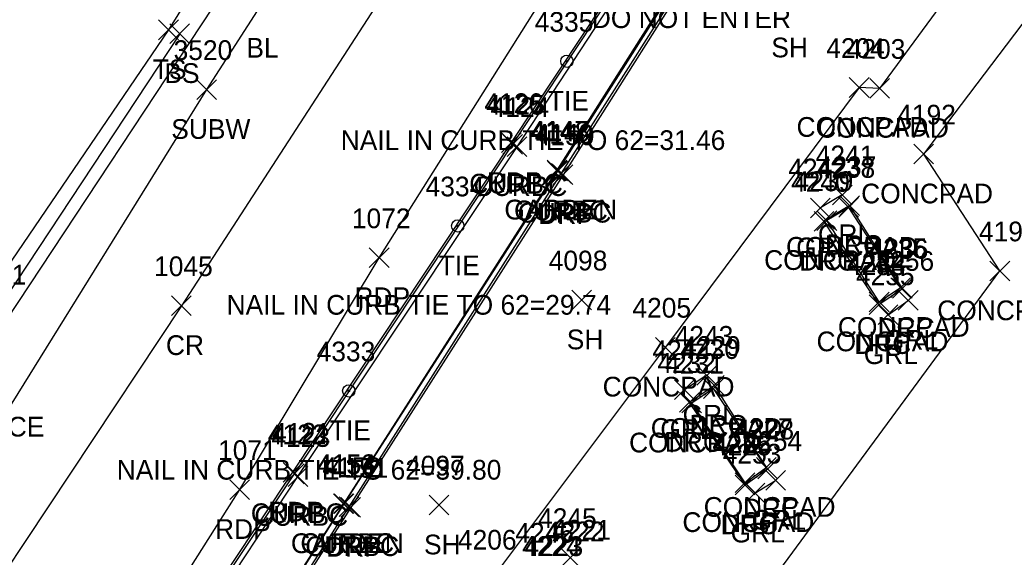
# Model space of a CAD drawing. Extents: x 1634209 to 1639641, y 608564 to 612258.
# Drawn here: x 1639153.3 to 1639254.2, y 611311.3 to 611365.7 of the extents above; entities that cross this region are included whole.
import ezdxf

# ---------------------------------------------------------------- set-up
doc = ezdxf.new("R2010")
doc.units = 0
for name, color, linetype in [('C_A', 7, 'Continuous'), ('C_C', 7, 'Continuous'), ('C_I', 7, 'Continuous'), ('CBP', 7, 'Continuous'), ('L_A', 7, 'Continuous'), ('L_I', 7, 'Continuous'), ('L_TIC', 7, 'Continuous'), ('LAPB', 7, 'Continuous'), ('LELB', 7, 'Continuous'), ('LS', 7, 'Continuous'), ('M_C', 7, 'Continuous'), ('P_A', 7, 'Continuous'), ('P_I', 7, 'Continuous'), ('P_TIC', 7, 'Continuous'), ('PET', 7, 'Continuous'), ('PRC', 7, 'Continuous'), ('R_A', 7, 'Continuous'), ('R_I', 7, 'Continuous'), ('R_TIC', 7, 'Continuous'), ('RC', 7, 'Continuous'), ('RDP', 7, 'Continuous'), ('RGR', 7, 'Continuous'), ('S_C', 7, 'Continuous'), ('U_A', 7, 'Continuous'), ('U_I', 7, 'Continuous'), ('U_TIC', 7, 'Continuous'), ('UW', 7, 'Continuous')]:
    doc.layers.add(name, color=color, linetype=linetype)

msp = doc.modelspace()

# ---------------------------------------------------------------- linework, layer by layer
at = {"layer": 'CBP'}
for centre, radius in [((1639208.81, 611361.54), 0.625), ((1639208.81, 611361.54), 0.0833), ((1639197.74, 611344.84), 0.625), ((1639197.74, 611344.84), 0.0833), ((1639186.69, 611328.11), 0.625), ((1639186.69, 611328.11), 0.0833)]:
    msp.add_circle(centre, radius, dxfattribs=at)
at = {"layer": 'L_TIC'}
for points in [[(1639167.4, 611363.73), (1639169.4, 611365.73)], [(1639169.4, 611363.73), (1639167.4, 611365.73)], [(1639168.54, 611363.34), (1639170.54, 611365.34)], [(1639170.54, 611363.34), (1639168.54, 611365.34)], [(1639237.46, 611357.88), (1639239.46, 611359.88)], [(1639239.46, 611357.88), (1639237.46, 611359.88)], [(1639239.54, 611357.79), (1639241.54, 611359.79)], [(1639241.54, 611357.79), (1639239.54, 611359.79)], [(1639244.01, 611351.13), (1639246.01, 611353.13)], [(1639246.01, 611351.13), (1639244.01, 611353.13)], [(1639206.8, 611349.5), (1639208.8, 611351.5)], [(1639208.8, 611349.5), (1639206.8, 611351.5)], [(1639236.4, 611345.72), (1639238.4, 611347.72)], [(1639238.4, 611345.72), (1639236.4, 611347.72)], [(1639234.18, 611344.38), (1639236.18, 611346.38)], [(1639236.18, 611344.38), (1639234.18, 611346.38)], [(1639234.18, 611344.38), (1639236.18, 611346.38)], [(1639236.18, 611344.38), (1639234.18, 611346.38)], [(1639251.73, 611339.28), (1639253.73, 611341.28)], [(1639253.73, 611339.28), (1639251.73, 611341.28)], [(1639241.66, 611337.59), (1639243.66, 611339.59)], [(1639243.66, 611337.59), (1639241.66, 611339.59)], [(1639209.31, 611336.33), (1639211.31, 611338.33)], [(1639211.31, 611336.33), (1639209.31, 611338.33)], [(1639239.49, 611336.13), (1639241.49, 611338.13)], [(1639241.49, 611336.13), (1639239.49, 611338.13)], [(1639239.49, 611336.13), (1639241.49, 611338.13)], [(1639241.49, 611336.13), (1639239.49, 611338.13)], [(1639217.8, 611331.54), (1639219.8, 611333.54)], [(1639219.8, 611331.54), (1639217.8, 611333.54)], [(1639222.67, 611327.35), (1639224.67, 611329.35)], [(1639224.67, 611327.35), (1639222.67, 611329.35)], [(1639220.48, 611325.87), (1639222.48, 611327.87)], [(1639222.48, 611325.87), (1639220.48, 611327.87)], [(1639220.48, 611325.87), (1639222.48, 611327.87)], [(1639222.48, 611325.87), (1639220.48, 611327.87)], [(1639228.04, 611319.34), (1639230.04, 611321.34)], [(1639230.04, 611319.34), (1639228.04, 611321.34)], [(1639225.88, 611317.8), (1639227.88, 611319.8)], [(1639227.88, 611317.8), (1639225.88, 611319.8)], [(1639225.88, 611317.8), (1639227.88, 611319.8)], [(1639227.88, 611317.8), (1639225.88, 611319.8)], [(1639185.15, 611315.66), (1639187.15, 611317.66)], [(1639187.15, 611315.66), (1639185.15, 611317.66)], [(1639194.84, 611315.53), (1639196.84, 611317.53)], [(1639196.84, 611315.53), (1639194.84, 611317.53)]]:
    msp.add_lwpolyline(points, dxfattribs=at)
at = {"layer": 'LAPB'}
msp.add_lwpolyline([(1639223.72, 611375.64), (1639207.8, 611350.5), (1639186.15, 611316.66), (1639169.99, 611291.33), (1639168.06, 611284.08), (1639167.91, 611278.79), (1639169.16, 611272.05), (1639187.9, 611242.79)], dxfattribs=at)
at = {"layer": 'LELB'}
for points in [[(1639184.5, 611390.62), (1639168.4, 611364.73), (1639149.1, 611336.39), (1639141.99, 611332.95), (1639134.34, 611331.83), (1639128.54, 611335.11), (1639121.61, 611339.72), (1639110.96, 611351.76), (1639096.78, 611371.21), (1639095.54, 611383.49), (1639101.79, 611394.14), (1639116.54, 611418.41), (1639131.91, 611444.98), (1639113.36, 611469.05), (1639093.12, 611490.67), (1639071.05, 611509.19), (1639055.5, 611526.42)], [(1639169.54, 611364.34), (1639150.74, 611335.9), (1639150.02, 611334.68), (1639147.96, 611333.12), (1639142.59, 611331.2), (1639134.1, 611329.89), (1639127.41, 611331.58), (1639119.27, 611337.17), (1639108.26, 611349.25)]]:
    msp.add_lwpolyline(points, dxfattribs=at)
at = {"layer": 'LS'}
for points in [[(1639197.35, 611268.33), (1639199.31, 611268.39), (1639210.97, 611284.28), (1639226, 611303.95), (1639252.73, 611340.28), (1639245.01, 611352.13), (1639262.63, 611375.38), (1639283.99, 611360.32), (1639285.88, 611360.67), (1639299.25, 611379.23), (1639299.14, 611381.16), (1639265.73, 611405.38), (1639263.88, 611405.03), (1639250.44, 611386.61), (1639250.46, 611384.53), (1639256.24, 611380.17), (1639240.54, 611358.79), (1639238.46, 611358.88), (1639218.8, 611332.54), (1639201.15, 611309.01), (1639184.63, 611286.63), (1639191.26, 611276.75)], [(1639240.49, 611337.13), (1639242.66, 611338.59), (1639237.4, 611346.72), (1639235.18, 611345.38)], [(1639240.49, 611337.13), (1639235.18, 611345.38)], [(1639226.88, 611318.8), (1639229.04, 611320.34), (1639223.67, 611328.35), (1639221.48, 611326.87)], [(1639226.88, 611318.8), (1639221.48, 611326.87)]]:
    msp.add_lwpolyline(points, dxfattribs=at)
at = {"layer": 'P_TIC'}
for points in [[(1639202.19, 611352.29), (1639204.19, 611354.29)], [(1639204.19, 611352.29), (1639202.19, 611354.29)], [(1639188.77, 611340.61), (1639190.77, 611342.61)], [(1639190.77, 611340.61), (1639188.77, 611342.61)], [(1639168.71, 611335.75), (1639170.71, 611337.75)], [(1639170.71, 611335.75), (1639168.71, 611337.75)], [(1639180.02, 611318.86), (1639182.02, 611320.86)], [(1639182.02, 611318.86), (1639180.02, 611320.86)], [(1639174.63, 611317.1), (1639176.63, 611319.1)], [(1639176.63, 611317.1), (1639174.63, 611319.1)]]:
    msp.add_lwpolyline(points, dxfattribs=at)
at = {"layer": 'PET'}
for points in [[(1639227.99, 611172.98), (1639228.32, 611174.39), (1639214.9, 611192.14), (1639202.86, 611208.11), (1639190.66, 611227), (1639183.08, 611239.21), (1639162.79, 611271), (1639160.92, 611274.86), (1639160.06, 611279.39), (1639160.11, 611285.35), (1639161.86, 611291.07), (1639181.02, 611319.86), (1639203.19, 611353.29), (1639219.74, 611378.25), (1639229.46, 611393.47), (1639239.19, 611407.62), (1639252.49, 611428.76), (1639267.88, 611454.5), (1639285.6, 611485.31)], [(1638854.83, 610853.22), (1638885.37, 610909), (1638902.82, 610937.28), (1638929.33, 610982.56), (1638950.92, 611019.42), (1638971.29, 611051.92), (1639000.04, 611096.96), (1639023.57, 611133.7), (1639039.12, 611159.19), (1639064.62, 611197.78), (1639080.51, 611223.3), (1639114.23, 611277.34), (1639131.17, 611302.28), (1639149.64, 611331.79), (1639176.42, 611372.35), (1639193.48, 611398.88), (1639220.96, 611441.47), (1639247.22, 611483.75)], [(1638878.4, 610839.82), (1638902.26, 610883.1), (1638925.76, 610925.06), (1638957.25, 610978.12), (1638978.73, 611014.12), (1639004.29, 611055.32), (1639040.97, 611112.28), (1639073.41, 611162.89), (1639072.72, 611163.46), (1639102.57, 611207.56), (1639124.27, 611240.99), (1639140.69, 611264.29), (1639156.2, 611287.4), (1639175.63, 611318.1), (1639189.77, 611341.61), (1639219.88, 611389.38), (1639245.26, 611428.04), (1639265.27, 611462.65)]]:
    msp.add_lwpolyline(points, dxfattribs=at)
at = {"layer": 'PRC'}
msp.add_lwpolyline([(1639250.46, 611462.84), (1639222.36, 611418.18), (1639195.34, 611376.28), (1639169.71, 611336.75), (1639147.17, 611302.78), (1639120.59, 611261.16), (1639092.55, 611217.83), (1639063.71, 611172.41), (1639032.46, 611123.7), (1639004.79, 611080.3), (1638977.88, 611037.27), (1638950.44, 610992.13), (1638925.96, 610950.29), (1638900.29, 610905.36), (1638879.75, 610869.2), (1638867.15, 610846.08)], dxfattribs=at)
at = {"layer": 'R_TIC'}
for points in [[(1639202.32, 611352.13), (1639204.32, 611354.13)], [(1639204.32, 611352.13), (1639202.32, 611354.13)], [(1639202.76, 611351.88), (1639204.76, 611353.88)], [(1639204.76, 611351.88), (1639202.76, 611353.88)], [(1639206.86, 611349.41), (1639208.86, 611351.41)], [(1639208.86, 611349.41), (1639206.86, 611351.41)], [(1639207.24, 611349.18), (1639209.24, 611351.18)], [(1639209.24, 611349.18), (1639207.24, 611351.18)], [(1639207.43, 611349.03), (1639209.43, 611351.03)], [(1639209.43, 611349.03), (1639207.43, 611351.03)], [(1639235.74, 611346.99), (1639237.74, 611348.99)], [(1639237.74, 611346.99), (1639235.74, 611348.99)], [(1639233.53, 611345.66), (1639235.53, 611347.66)], [(1639235.53, 611345.66), (1639233.53, 611347.66)], [(1639236.51, 611345.9), (1639238.51, 611347.9)], [(1639238.51, 611345.9), (1639236.51, 611347.9)], [(1639233.89, 611344.31), (1639235.89, 611346.31)], [(1639235.89, 611344.31), (1639233.89, 611346.31)], [(1639233.89, 611344.31), (1639235.89, 611346.31)], [(1639235.89, 611344.31), (1639233.89, 611346.31)], [(1639241.84, 611337.51), (1639243.84, 611339.51)], [(1639243.84, 611337.51), (1639241.84, 611339.51)], [(1639242.43, 611336.29), (1639244.43, 611338.29)], [(1639244.43, 611336.29), (1639242.43, 611338.29)], [(1639239.47, 611335.86), (1639241.47, 611337.86)], [(1639241.47, 611335.86), (1639239.47, 611337.86)], [(1639239.47, 611335.86), (1639241.47, 611337.86)], [(1639241.47, 611335.86), (1639239.47, 611337.86)], [(1639240.39, 611334.83), (1639242.39, 611336.83)], [(1639242.39, 611334.83), (1639240.39, 611336.83)], [(1639222.01, 611328.69), (1639224.01, 611330.69)], [(1639224.01, 611328.69), (1639222.01, 611330.69)], [(1639219.74, 611327.23), (1639221.74, 611329.23)], [(1639221.74, 611327.23), (1639219.74, 611329.23)], [(1639222.77, 611327.66), (1639224.77, 611329.66)], [(1639224.77, 611327.66), (1639222.77, 611329.66)], [(1639220.25, 611325.94), (1639222.25, 611327.94)], [(1639222.25, 611325.94), (1639220.25, 611327.94)], [(1639220.25, 611325.94), (1639222.25, 611327.94)], [(1639222.25, 611325.94), (1639220.25, 611327.94)], [(1639228.17, 611319.19), (1639230.17, 611321.19)], [(1639230.17, 611319.19), (1639228.17, 611321.19)], [(1639180.17, 611318.7), (1639182.17, 611320.7)], [(1639182.17, 611318.7), (1639180.17, 611320.7)], [(1639180.53, 611318.43), (1639182.53, 611320.43)], [(1639182.53, 611318.43), (1639180.53, 611320.43)], [(1639228.99, 611318.03), (1639230.99, 611320.03)], [(1639230.99, 611318.03), (1639228.99, 611320.03)], [(1639225.89, 611317.57), (1639227.89, 611319.57)], [(1639227.89, 611317.57), (1639225.89, 611319.57)], [(1639225.89, 611317.57), (1639227.89, 611319.57)], [(1639227.89, 611317.57), (1639225.89, 611319.57)], [(1639226.88, 611316.74), (1639228.88, 611318.74)], [(1639228.88, 611316.74), (1639226.88, 611318.74)], [(1639185.2, 611315.67), (1639187.2, 611317.67)], [(1639187.2, 611315.67), (1639185.2, 611317.67)], [(1639185.7, 611315.36), (1639187.7, 611317.36)], [(1639187.7, 611315.36), (1639185.7, 611317.36)], [(1639185.89, 611315.3), (1639187.89, 611317.3)], [(1639187.89, 611315.3), (1639185.89, 611317.3)], [(1639208.15, 611310.2), (1639210.15, 611312.2)], [(1639210.15, 611310.2), (1639208.15, 611312.2)]]:
    msp.add_lwpolyline(points, dxfattribs=at)
at = {"layer": 'RC'}
for points in [[(1639183.21, 611239.37), (1639162.96, 611271.11), (1639161.11, 611274.87), (1639160.3, 611279.33), (1639160.35, 611285.37), (1639162.06, 611290.92), (1639181.17, 611319.7), (1639203.32, 611353.13), (1639219.91, 611378.2)], [(1639183.57, 611239.62), (1639163.34, 611271.33), (1639161.58, 611275.05), (1639160.84, 611279.26), (1639160.77, 611285.27), (1639162.51, 611290.63), (1639181.53, 611319.43), (1639203.76, 611352.88), (1639220.25, 611377.98)], [(1639223.9, 611375.6), (1639207.86, 611350.41), (1639186.2, 611316.67), (1639170.12, 611291.28), (1639168.12, 611284.06), (1639167.97, 611278.79), (1639169.31, 611272.15), (1639188.08, 611242.69), (1639188.48, 611241.05), (1639187.63, 611239.54), (1639186.19, 611238.72), (1639184.76, 611238.74)], [(1639223.9, 611374.83), (1639208.24, 611350.18), (1639186.7, 611316.36), (1639170.39, 611290.97), (1639168.66, 611283.95), (1639168.39, 611278.81), (1639169.67, 611272.55), (1639188.4, 611242.94), (1639188.95, 611241.07), (1639187.87, 611239.17), (1639186.43, 611238.42), (1639184.55, 611238.31)]]:
    msp.add_lwpolyline(points, dxfattribs=at)
at = {"layer": 'RDP'}
for points in [[(1639219.74, 611378.25), (1639221.32, 611379.7), (1639222.71, 611379.98), (1639224.56, 611378.99), (1639225.1, 611377.16), (1639224.08, 611374.74), (1639208.43, 611350.03), (1639186.89, 611316.3), (1639170.7, 611291), (1639168.85, 611283.92), (1639168.67, 611278.87), (1639169.84, 611272.62), (1639188.64, 611243.07), (1639189.11, 611241.01), (1639188.02, 611239.09), (1639186.51, 611238.29), (1639184.57, 611238.1)], [(1639240.47, 611336.86), (1639242.84, 611338.51), (1639237.51, 611346.9), (1639234.89, 611345.31)], [(1639240.47, 611336.86), (1639234.89, 611345.31)], [(1639226.89, 611318.57), (1639229.17, 611320.19), (1639223.77, 611328.66), (1639221.25, 611326.94)], [(1639226.89, 611318.57), (1639221.25, 611326.94)]]:
    msp.add_lwpolyline(points, dxfattribs=at)
at = {"layer": 'RGR'}
for points in [[(1639236.74, 611347.99), (1639234.53, 611346.66)], [(1639241.39, 611335.83), (1639243.43, 611337.29)], [(1639223.01, 611329.69), (1639220.74, 611328.23)], [(1639227.88, 611317.74), (1639229.99, 611319.03)]]:
    msp.add_lwpolyline(points, dxfattribs=at)
at = {"layer": 'U_TIC'}
for points in [[(1639171.27, 611357.67), (1639173.27, 611359.67)], [(1639173.27, 611357.67), (1639171.27, 611359.67)]]:
    msp.add_lwpolyline(points, dxfattribs=at)
at = {"layer": 'UW'}
msp.add_lwpolyline([(1639594.99, 612226.51), (1639569.63, 612190.35), (1639550.67, 612164.48), (1639527.14, 612128.9), (1639506.92, 612097.5), (1639485.03, 612062.24), (1639463.29, 612024.05), (1639448.18, 611991.92), (1639428.21, 611945.59), (1639409.39, 611896.28), (1639395.47, 611852.57), (1639388.14, 611826.68), (1639366.36, 611747.21), (1639350.92, 611692.02), (1639316.38, 611597.42), (1639292.15, 611550.99), (1639279.15, 611528.72), (1639253.95, 611487.01), (1639229.78, 611449.06), (1639200.46, 611402.5), (1639172.27, 611358.67), (1639148.82, 611320.98)], dxfattribs=at)

# ---------------------------------------------------------------- texts
at = {"layer": 'C_A'}
for s, p in [('BL', (1639176.3, 611361.91)), ('TIE', (1639206.89, 611356.54)), ('TIE', (1639195.82, 611339.84)), ('TIE', (1639184.77, 611323.11))]:
    msp.add_text(s, height=2, dxfattribs=at).set_placement(p)
at = {"layer": 'C_C'}
for s, p in [('NAIL IN CURB TIE TO 62=31.46', (1639185.87, 611352.54)), ('NAIL IN CURB TIE TO 62=29.74', (1639174.29, 611335.84)), ('NAIL IN CURB TIE TO 62=39.80', (1639163.15, 611319.11))]:
    msp.add_text(s, height=2, dxfattribs=at).set_placement(p)
at = {"layer": 'C_I'}
for s, p in [('4335', (1639205.55, 611364.54)), ('4334', (1639194.48, 611347.84)), ('4333', (1639183.43, 611331.11))]:
    msp.add_text(s, height=2, dxfattribs=at).set_placement(p)
at = {"layer": 'L_A'}
for s, p in [('SH', (1639229.55, 611361.94)), ('TS', (1639166.81, 611359.73)), ('BS', (1639167.98, 611359.34)), ('CONCPAD', (1639232.11, 611353.88)), ('CONCPAD', (1639234.19, 611353.79)), ('CONCPAD', (1639238.66, 611347.13)), ('GARDEN', (1639202.47, 611345.5)), ('CONCPAD', (1639231.04, 611341.72)), ('CONCPAD', (1639228.82, 611340.38)), ('CONCPAD', (1639228.82, 611340.38)), ('CONCPAD', (1639246.38, 611335.28)), ('CONCPAD', (1639236.3, 611333.59)), ('SH', (1639208.8, 611332.33)), ('CONCPAD', (1639234.14, 611332.13)), ('CONCPAD', (1639234.14, 611332.13)), ('CONCPAD', (1639212.44, 611327.54)), ('CONCPAD', (1639217.32, 611323.35)), ('CONCPAD', (1639215.12, 611321.87)), ('CONCPAD', (1639215.12, 611321.87)), ('CONCPAD', (1639222.69, 611315.34)), ('CONCPAD', (1639220.53, 611313.8)), ('CONCPAD', (1639220.53, 611313.8)), ('GARDEN', (1639180.82, 611311.66)), ('SH', (1639194.32, 611311.53))]:
    msp.add_text(s, height=2, dxfattribs=at).set_placement(p)
at = {"layer": 'L_I'}
for s, p in [('4204', (1639235.12, 611361.88)), ('4203', (1639237.2, 611361.79)), ('4192', (1639242.32, 611355.13)), ('4147', (1639205.11, 611353.5)), ('4238', (1639234.14, 611349.72)), ('4239', (1639231.91, 611348.38)), ('4239', (1639231.91, 611348.38)), ('4191', (1639250.61, 611343.28)), ('4235', (1639239.4, 611341.59)), ('4098', (1639206.97, 611340.33)), ('4234', (1639237.23, 611340.13)), ('4234', (1639237.23, 611340.13)), ('3731', (1639148.04, 611338.9)), ('4205', (1639215.46, 611335.54)), ('4230', (1639220.32, 611331.35)), ('4231', (1639218.78, 611329.87)), ('4231', (1639218.78, 611329.87)), ('4227', (1639225.78, 611323.34)), ('4226', (1639223.57, 611321.8)), ('4226', (1639223.57, 611321.8)), ('4154', (1639183.46, 611319.66)), ('4097', (1639192.5, 611319.53)), ('4222', (1639206.68, 611312.85)), ('4206', (1639197.76, 611312.01)), ('4223', (1639204.52, 611311.36)), ('4223', (1639204.52, 611311.36))]:
    msp.add_text(s, height=2, dxfattribs=at).set_placement(p)
at = {"layer": 'M_C'}
msp.add_text('IRON ROD W/CAP W.LAWRENCE', height=2, dxfattribs=at).set_placement((1639113.76, 611323.48))
at = {"layer": 'P_A'}
for s, p in [('RDP', (1639200.68, 611348.29)), ('RDP', (1639187.26, 611336.61)), ('CR', (1639168.14, 611331.75)), ('RDP', (1639178.51, 611314.86)), ('RDP', (1639173.12, 611313.1))]:
    msp.add_text(s, height=2, dxfattribs=at).set_placement(p)
at = {"layer": 'P_I'}
for s, p in [('4126', (1639200.45, 611356.29)), ('1072', (1639187, 611344.61)), ('1045', (1639166.94, 611339.75)), ('4121', (1639178.9, 611322.86)), ('1071', (1639173.43, 611321.1))]:
    msp.add_text(s, height=2, dxfattribs=at).set_placement(p)
at = {"layer": 'R_A'}
for s, p in [('CURBC', (1639198.9, 611348.13)), ('CURBC', (1639199.35, 611347.88)), ('CURBC', (1639203.45, 611345.41)), ('CURBC', (1639203.82, 611345.18)), ('DRP', (1639205.91, 611345.03)), ('GRL', (1639234.28, 611342.99)), ('GRL', (1639232.07, 611341.66)), ('DRC', (1639234.99, 611341.9)), ('DRC', (1639232.38, 611340.31)), ('DRC', (1639232.38, 611340.31)), ('DRC', (1639240.33, 611333.51)), ('GRL', (1639240.97, 611332.29)), ('DRC', (1639237.95, 611331.86)), ('DRC', (1639237.95, 611331.86)), ('GRL', (1639238.93, 611330.83)), ('GRL', (1639220.55, 611324.69)), ('GRL', (1639218.29, 611323.23)), ('DRC', (1639221.26, 611323.66)), ('DRC', (1639218.74, 611321.94)), ('DRC', (1639218.74, 611321.94)), ('DRC', (1639226.65, 611315.19)), ('CURBC', (1639176.75, 611314.7)), ('CURBC', (1639177.11, 611314.43)), ('GRL', (1639227.54, 611314.03)), ('DRC', (1639224.38, 611313.57)), ('DRC', (1639224.38, 611313.57)), ('GRL', (1639225.42, 611312.74)), ('CURBC', (1639181.78, 611311.67)), ('CURBC', (1639182.28, 611311.36)), ('DRP', (1639184.38, 611311.3))]:
    msp.add_text(s, height=2, dxfattribs=at).set_placement(p)
at = {"layer": 'R_I'}
for s, p in [('4125', (1639200.62, 611356.13)), ('4124', (1639201.07, 611355.88)), ('4148', (1639205.17, 611353.41)), ('4149', (1639205.54, 611353.18)), ('4150', (1639205.65, 611353.03)), ('4241', (1639234.05, 611350.99)), ('4242', (1639231.27, 611349.66)), ('4237', (1639234.25, 611349.9)), ('4240', (1639231.55, 611348.31)), ('4240', (1639231.55, 611348.31)), ('4236', (1639239.53, 611341.51)), ('4256', (1639240.12, 611340.29)), ('4233', (1639237.21, 611339.86)), ('4233', (1639237.21, 611339.86)), ('4255', (1639238.13, 611338.83)), ('4243', (1639219.75, 611332.69)), ('4244', (1639217.49, 611331.23)), ('4229', (1639220.5, 611331.66)), ('4232', (1639217.99, 611329.94)), ('4232', (1639217.99, 611329.94)), ('4228', (1639225.91, 611323.19)), ('4122', (1639178.47, 611322.7)), ('4123', (1639178.84, 611322.43)), ('4254', (1639226.73, 611322.03)), ('4225', (1639223.63, 611321.57)), ('4225', (1639223.63, 611321.57)), ('4253', (1639224.62, 611320.74)), ('4153', (1639183.5, 611319.67)), ('4152', (1639184.01, 611319.36)), ('4151', (1639184.76, 611319.3)), ('4245', (1639205.89, 611314.2)), ('4221', (1639207.33, 611313.02)), ('4246', (1639203.58, 611312.71)), ('4224', (1639204.28, 611311.38)), ('4224', (1639204.28, 611311.38))]:
    msp.add_text(s, height=2, dxfattribs=at).set_placement(p)
at = {"layer": 'S_C'}
msp.add_text('DO NOT ENTER', height=2, dxfattribs=at).set_placement((1639211.34, 611364.91))
at = {"layer": 'U_A'}
msp.add_text('SUBW', height=2, dxfattribs=at).set_placement((1639168.68, 611353.67))
at = {"layer": 'U_I'}
msp.add_text('3520', height=2, dxfattribs=at).set_placement((1639168.92, 611361.67))

doc.saveas('drawing.dxf')
